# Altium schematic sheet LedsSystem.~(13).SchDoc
size A4
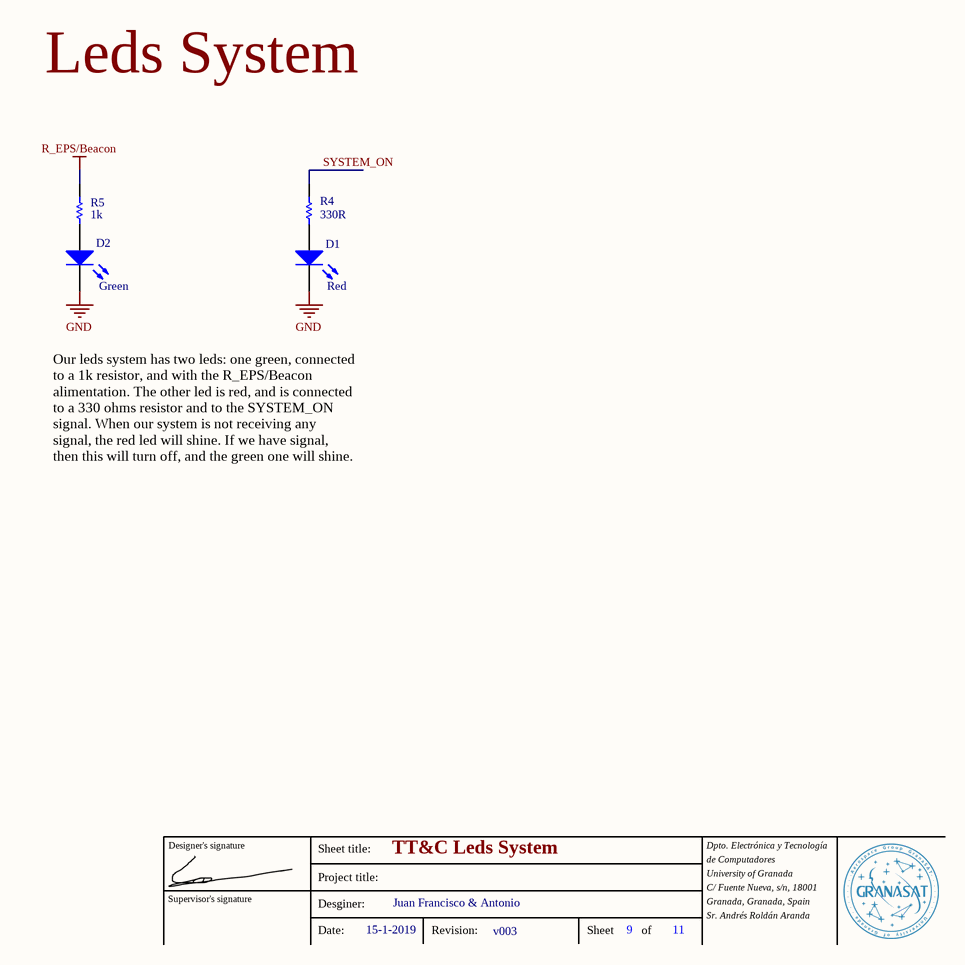
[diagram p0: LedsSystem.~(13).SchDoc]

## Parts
D1  Red  [LEDR]
D2  Green  [LEDG]
R4  value 330R  [R330]
R5  1k  [R1k]

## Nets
GND: D1.2(K) D2.2(K)
R_EPS/Beacon: R5.2
SYSTEM_ON: R4.2

Not connected (* = marked no-connect by the designer): D1 1(A); D2 1(A); R4 1; R5 1

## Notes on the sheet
- Leds System
- Our leds system has two leds: one green, connected to a 1k resistor, and with the R_EPS/Beacon alimentation. The other led is red, and is connected to a 330 ohms resistor and to the SYSTEM_ON signal. When our system is not receiving any signal, the red led will shine. If we have signal, then this will turn off, and the green one will shine.
- Designer's signature
- Sheet title:
- TT&C Leds System
- Dpto. Electrónica y Tecnología
- de Computadores
- Supervisor's signature
- Project title:
- Desginer:
- Juan Francisco & Antonio
- University of Granada
- C/ Fuente Nueva, s/n, 18001
- Granada, Granada, Spain
- Sr. Andrés Roldán Aranda
- Date:
- 15-1-2019
- Revision:
- v003
- Sheet
- 9
- of
- 11

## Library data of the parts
D1 D2 = LED2: Typical RED, GREEN, YELLOW, AMBER GaAs LED
R4 R5 = Res1: Resistor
